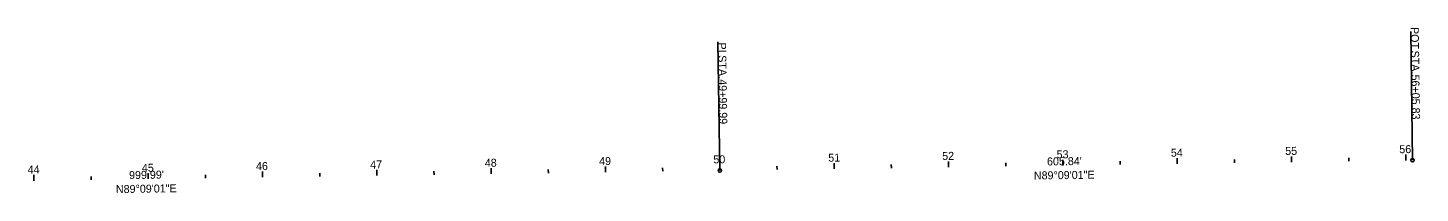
# Model space of a CAD drawing. Extents: x 1805326 to 1810276, y 297762 to 303660.
# Drawn here: x 1809059 to 1810276, y 298369 to 298514 of the extents above; entities that cross this region are included whole.
import ezdxf

# ---------------------------------------------------------------- set-up
doc = ezdxf.new("R2010")
doc.units = 0
for name, color, linetype in [('GE_P_Alignment_100_Bearings', 7, 'Continuous'), ('GE_P_Alignment_100_Cardinal_Points', 7, 'Continuous'), ('GE_P_Alignment_100_Distances', 7, 'Continuous'), ('GE_P_Alignment_100_Stations', 7, 'Continuous')]:
    doc.layers.add(name, color=color, linetype=linetype)

msp = doc.modelspace()

# ---------------------------------------------------------------- linework, layer by layer
at = {"layer": 'GE_P_Alignment_100_Cardinal_Points'}
for p, q in [((1810269.7, 298397.8), (1810268.1, 298510.3)), ((1809664, 298388.8), (1809662.3, 298501.3))]:
    msp.add_line(p, q, dxfattribs=at)
for centre in [(1810269.7, 298397.8), (1809664, 298388.8)]:
    msp.add_circle(centre, 1.5, dxfattribs=at)
at = {"layer": 'GE_P_Alignment_100_Stations'}
for p, q in [((1809863.9, 298391.8), (1809863.9, 298396.8)), ((1809963.9, 298393.3), (1809963.9, 298398.3)), ((1810013.9, 298394), (1810013.9, 298397)), ((1810063.9, 298394.7), (1810063.8, 298399.7)), ((1810113.9, 298395.5), (1810113.9, 298398.5)), ((1810163.9, 298396.2), (1810163.8, 298401.2)), ((1810213.9, 298397), (1810213.9, 298400)), ((1810263.9, 298397.7), (1810263.8, 298402.7)), ((1809064, 298379.9), (1809064, 298384.9)), ((1809164, 298381.4), (1809163.9, 298386.4)), ((1809214, 298382.1), (1809214, 298385.1)), ((1809264, 298382.9), (1809263.9, 298387.9)), ((1809314, 298383.6), (1809314, 298386.6)), ((1809364, 298384.4), (1809363.9, 298389.4)), ((1809414, 298385.1), (1809413.9, 298388.1)), ((1809464, 298385.9), (1809463.9, 298390.9)), ((1809514, 298386.6), (1809513.9, 298389.6)), ((1809564, 298387.3), (1809563.9, 298392.3)), ((1809614, 298388.1), (1809613.9, 298391.1)), ((1809664, 298388.8), (1809663.9, 298393.8)), ((1809714, 298389.6), (1809713.9, 298392.6)), ((1809764, 298390.3), (1809763.9, 298395.3)), ((1809814, 298391), (1809813.9, 298394)), ((1809913.9, 298392.5), (1809913.9, 298395.5)), ((1809114, 298380.7), (1809114, 298383.7))]:
    msp.add_line(p, q, dxfattribs=at)

# ---------------------------------------------------------------- texts
at = {"layer": 'GE_P_Alignment_100_Bearings'}
for rotation, p in [(0.8497, (1809938.6, 298380.9)), (0.8496, (1809135.8, 298369))]:
    msp.add_text('N89°09\'01"E', height=7, rotation=rotation, dxfattribs=at).set_placement(p)
at = {"layer": 'GE_P_Alignment_100_Cardinal_Points'}
for s, p in [('POT', (1810268.1, 298514.3)), ('PI', (1809662.4, 298500.7)), (' STA. ', (1809662.5, 298492.2)), (' STA. ', (1810268.4, 298496.3)), ('56+05.83', (1810268.7, 298472.7)), ('49+99.99', (1809662.9, 298468.6))]:
    msp.add_text(s, height=7, rotation=270.8497, dxfattribs=at).set_placement(p)
at = {"layer": 'GE_P_Alignment_100_Distances'}
for s, rotation, p in [("605.84'", 0.8497, (1809950.1, 298393.2)), ("999.99'", 0.8496, (1809147.3, 298381.3))]:
    msp.add_text(s, height=7, rotation=rotation, dxfattribs=at).set_placement(p)
at = {"layer": 'GE_P_Alignment_100_Stations'}
for s, rotation, p in [('55', 0.8497, (1810158.4, 298402.4)), ('56', 0.8497, (1810258.2, 298403.9)), ('47', 0.8496, (1809358.2, 298390.5)), ('48', 0.8496, (1809458.4, 298392)), ('49', 0.8496, (1809558.4, 298393.5)), ('50', 0.8497, (1809658.3, 298395)), ('51', 0.8497, (1809758.8, 298396.5)), ('52', 0.8497, (1809858.4, 298398)), ('53', 0.8497, (1809958.5, 298399.4)), ('54', 0.8497, (1810058.4, 298400.9)), ('44', 0.8496, (1809058.6, 298386.1)), ('45', 0.8496, (1809158.5, 298387.6)), ('46', 0.8496, (1809258.3, 298389.1))]:
    msp.add_text(s, height=7, rotation=rotation, dxfattribs=at).set_placement(p)

doc.saveas('drawing.dxf')
